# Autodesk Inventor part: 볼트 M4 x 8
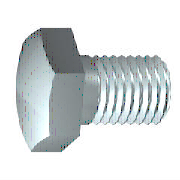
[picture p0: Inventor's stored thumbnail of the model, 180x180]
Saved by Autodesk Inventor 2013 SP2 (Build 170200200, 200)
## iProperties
Created: 2012-02
Part Number: 볼트 M4 x 8
Material: 스테인리스강
Description: 6각 머리 나사
Document SubType Name: Modeling
Standard: ISO 4017
Designer: mduedu
Standard Revision: Third edition 1999-08-15
Standards Organization: ISO
Language: ko-KR
Size Designation: M4 x 10
Categories: <MemberInstance><Categories><Category DisplayName="조임쇠" InternalName="e4da775c-781d-43d5-af7c-5136215cf5a6" Mnemonic="FSTN"><Category DisplayName="볼트" InternalN
Density: 8.08 g/cm^3
IsCustomPart: 0
Author: mduedu
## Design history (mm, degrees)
sketch "스케치1"
  geometry: L1 (0, 3.015)-(0, 2); L2 (1.75, 2)-(8, 2); L3 (8, 2)-(8, 0); L4 (8, 0)-(-0.4, 0); L5 (-2.08, 0)-(9.68, 0) reference; L6 (-0.4, 0)-(-0.4, 3.015); L7 (-0.4, 3.015)-(0, 3.015); L8 (1.75, 2)-(1.32, 2); L9 (1.32, 2)-(0, 2); L10 (0, -0.603)-(0, 3.618) reference
  constraints: 16 end point, 2 collinear, 2 perpendicular, 1 parallel
  dimensions: "d0" = 8 distance between parallel lines of L3 L1 (= NLG); "d1" = 6.25 distance from line of L2.start L3 (= GEL); "d2" = 4 diameter of L2 L4 (= GD); "d9" = 0.4001 distance between parallel lines of L6 L1 (computed from SD); "d10" = 6.03 diameter of L7 L4 (= SD2); "d13" = 0.42952 distance of L2.start L8.end (computed from GAL); "d14" = 4 diameter of L9 L4 (= BDM)
revolve "본체" sketch "스케치1" stored, may be unused: angle "d12" = 90 deg
sketch "스케치2"
  geometry: L1 (0, 4.041)-(3.5, 2.021); L2 (3.5, 2.021)-(3.5, -2.021); L3 (3.5, -2.021)-(0, -4.041); L4 (0, -4.041)-(-3.5, -2.021); L5 (-3.5, -2.021)-(-3.5, 2.021); L6 (-3.5, 2.021)-(0, 4.041); 2 further points
  constraints: 12 end point, 1 coincident, 1 vertical, 11 other
  dimensions: "d11" = 7 distance between parallel lines of L5 L2 (= SW)
extrude "머리" join sketch "스케치2" distance "d3" = 2.4 (= KOH - SD); taper "d4" = 0 deg
sketch "스케치4"
  geometry: L1 (-2.8, 3.5)-(-2.8, 4.041); L2 (-2.8, 4.041)-(-2.487, 4.041); L3 (-2.487, 4.041)-(-2.8, 3.5); L4 (-3.28, 0)-(0.08, 0) reference; L5 (-0.4, 4.041)-(-2.8, 4.041) reference; L6 (-2.8, 2.021)-(-2.8, 4.041) reference
  constraints: 6 end point, 2 collinear, 1 perpendicular, 1 vertical
  dimensions: "d5" = 30 deg angle of L3 L1 (= ANG1); "d19" = 7 diameter of L1.start L4 (= SW0)
revolve "모따기1" sketch "스케치4" stored, may be unused: angle "d21" = 90 deg
workplane "Work Plane1"
body "Solid1"
feature "스레드" dims "d15" = 6.25 (= GEL), "d16" = 0
chamfer "모따기2" distance "d6" = 0.42941 (= -0.5 x SPD + 0.5 x GD); stored, may be unused: second distance "d7" = 0.42952 (computed from GUL), angle "d55" = 45 deg
other parameters: "NLG" = 8 [user parameter; used in 1 equation term], "GD" = 4 (= NND) [user parameter; used in 2 equation terms], "BDM" = 4 (= NND) [user parameter; used in 1 equation term], "KOH" = 2.8 [user parameter; used in 1 equation term], "GEL" = 6.25 [user parameter; used in 2 equation terms], "SW" = 7 [user parameter; used in 2 equation terms], "SW0" = 7 (= SW) [user parameter; used in 1 equation term], "SPD" = 3.14117 (= NND - 1.2269 x PTC) [user parameter; used in 1 equation term], "SD2" = 6.03 [user parameter; used in 2 equation terms], "SD" = 0.4 [user parameter; used in 2 equation terms], "ANG1" = 30 deg [user parameter; used in 1 equation term], "GAL" = 0.42941 (= 0.61345 x PTC) [user parameter; used in 1 equation term], "GUL" = 0.42941 (= 0.61345 x PTC) [user parameter; used in 1 equation term], "d8" = 0, "RR" = 0.2 [user parameter], "d57" = 0, "d58" = 0, "TPU" = 14.28571 (computed from PTC) [user parameter], "GD1" = 3.14117 (= THREADDIA - 1.2269 x PTC) [user parameter], "THREADDIA" = 4 [user parameter; used in 1 equation term], "SDH" = 6.03 (= SD2) [user parameter], "SDHG" = 2.1 [user parameter], "TOA" = 30 deg [user parameter], "PTC" = 0.7 [user parameter; used in 5 equation terms], "NND" = 4 [user parameter; used in 3 equation terms], "E0" = 8.085 [user parameter]
